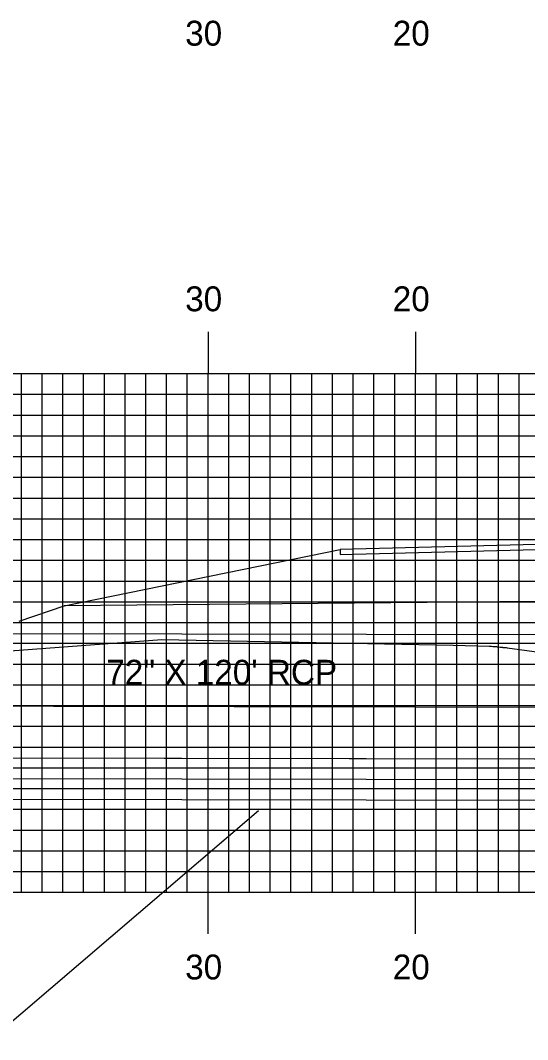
# Model space of a CAD drawing. Extents: x 1774777 to 1775120, y 442591 to 442811.
# Drawn here: x 1774903.64 to 1774928.1, y 442641.57 to 442690.68 of the extents above; entities that cross this region are included whole.
import ezdxf

# ---------------------------------------------------------------- set-up
doc = ezdxf.new("R2010")
doc.units = 0
for name, color, linetype in [('ANNOTATION', 7, 'Continuous'), ('D_Drainage_Culvert', 7, 'Continuous'), ('D_Drainage_Text', 7, 'Continuous'), ('D_Roadway_Edge_Shoulder', 7, 'Continuous'), ('D_Roadway_FinishedGrade', 7, 'Continuous'), ('H_V ANNOTATION', 7, 'Continuous'), ('MAJOR', 7, 'Continuous'), ('MINOR', 7, 'Continuous'), ('S_Roadway_Centerline', 7, 'Continuous')]:
    doc.layers.add(name, color=color, linetype=linetype)

msp = doc.modelspace()

# ---------------------------------------------------------------- linework, layer by layer
at = {"layer": 'ANNOTATION'}
msp.add_lwpolyline([(1774978.969, 442661.903), (1774956.856, 442662.454), (1774942.683, 442662.807), (1774928.511, 442662.681), (1774905.753, 442662.477)], dxfattribs=at)
at = {"layer": 'D_Drainage_Culvert'}
for p, q in [((1774883.795, 442661.172), (1774999.794, 442660.965)), ((1774883.784, 442655.172), (1774999.784, 442654.965)), ((1774883.784, 442654.179), (1774999.784, 442653.972)), ((1774883.784, 442653.179), (1774999.784, 442652.972))]:
    msp.add_line(p, q, dxfattribs=at)
for points in [[(1774883.784, 442655.172), (1774999.784, 442654.965), (1774999.784, 442654.971)], [(1774898.671, 442641.566), (1774902.195, 442641.566), (1774915.113, 442652.609)]]:
    msp.add_lwpolyline(points, dxfattribs=at)
at = {"layer": 'D_Roadway_Edge_Shoulder'}
msp.add_lwpolyline([(1774928.508, 442665.431), (1774919.057, 442665.186), (1774919.057, 442664.936), (1774928.508, 442665.181)], close=True, dxfattribs=at)
at = {"layer": 'D_Roadway_FinishedGrade'}
for p, q in [((1774905.753, 442662.477), (1774919.057, 442665.186)), ((1774903.585, 442661.737), (1774905.753, 442662.477))]:
    msp.add_line(p, q, dxfattribs=at)
msp.add_lwpolyline([(1774887.788, 442657.665), (1775009.789, 442657.447), (1775009.788, 442654.965), (1775009.788, 442652.965)], dxfattribs=at)
at = {"layer": 'MAJOR'}
for p, q in [((1774912.685, 442675.669), (1774912.685, 442673.665)), ((1774922.685, 442675.669), (1774922.685, 442673.665)), ((1774802.685, 442673.665), (1775082.685, 442673.665)), ((1774802.685, 442673.665), (1775082.685, 442673.665)), ((1774912.685, 442648.665), (1774912.685, 442673.665)), ((1774922.685, 442648.665), (1774922.685, 442673.665)), ((1774802.685, 442668.665), (1775082.685, 442668.665)), ((1774802.685, 442663.665), (1775082.685, 442663.665)), ((1774802.685, 442658.665), (1775082.685, 442658.665)), ((1774802.685, 442653.665), (1775082.685, 442653.665)), ((1774802.685, 442648.665), (1775082.685, 442648.665)), ((1774802.685, 442648.665), (1775082.685, 442648.665)), ((1774912.685, 442646.661), (1774912.685, 442648.665)), ((1774922.685, 442646.661), (1774922.685, 442648.665))]:
    msp.add_line(p, q, dxfattribs=at)
at = {"layer": 'MINOR'}
for p, q in [((1774903.685, 442648.665), (1774903.685, 442673.665)), ((1774904.685, 442648.665), (1774904.685, 442673.665)), ((1774905.685, 442648.665), (1774905.685, 442673.665)), ((1774906.685, 442648.665), (1774906.685, 442673.665)), ((1774907.685, 442648.665), (1774907.685, 442673.665)), ((1774908.685, 442648.665), (1774908.685, 442673.665)), ((1774909.685, 442648.665), (1774909.685, 442673.665)), ((1774910.685, 442648.665), (1774910.685, 442673.665)), ((1774911.685, 442648.665), (1774911.685, 442673.665)), ((1774913.685, 442648.665), (1774913.685, 442673.665)), ((1774914.685, 442648.665), (1774914.685, 442673.665)), ((1774915.685, 442648.665), (1774915.685, 442673.665)), ((1774916.685, 442648.665), (1774916.685, 442673.665)), ((1774917.685, 442648.665), (1774917.685, 442673.665)), ((1774918.685, 442648.665), (1774918.685, 442673.665)), ((1774919.685, 442648.665), (1774919.685, 442673.665)), ((1774920.685, 442648.665), (1774920.685, 442673.665)), ((1774921.685, 442648.665), (1774921.685, 442673.665)), ((1774923.685, 442648.665), (1774923.685, 442673.665)), ((1774924.685, 442648.665), (1774924.685, 442673.665)), ((1774925.685, 442648.665), (1774925.685, 442673.665)), ((1774926.685, 442648.665), (1774926.685, 442673.665)), ((1774927.685, 442648.665), (1774927.685, 442673.665)), ((1774802.685, 442672.665), (1775082.685, 442672.665)), ((1774802.685, 442671.665), (1775082.685, 442671.665)), ((1774802.685, 442670.665), (1775082.685, 442670.665)), ((1774802.685, 442669.665), (1775082.685, 442669.665)), ((1774802.685, 442667.665), (1775082.685, 442667.665)), ((1774802.685, 442666.665), (1775082.685, 442666.665)), ((1774802.685, 442665.665), (1775082.685, 442665.665)), ((1774802.685, 442664.665), (1775082.685, 442664.665)), ((1774802.685, 442662.665), (1775082.685, 442662.665)), ((1774802.685, 442661.665), (1775082.685, 442661.665)), ((1774802.685, 442660.665), (1775082.685, 442660.665)), ((1774802.685, 442659.665), (1775082.685, 442659.665)), ((1774802.685, 442657.665), (1775082.685, 442657.665)), ((1774802.685, 442656.665), (1775082.685, 442656.665)), ((1774802.685, 442655.665), (1775082.685, 442655.665)), ((1774802.685, 442654.665), (1775082.685, 442654.665)), ((1774802.685, 442652.665), (1775082.685, 442652.665)), ((1774802.685, 442651.665), (1775082.685, 442651.665)), ((1774802.685, 442650.665), (1775082.685, 442650.665)), ((1774802.685, 442649.665), (1775082.685, 442649.665))]:
    msp.add_line(p, q, dxfattribs=at)
at = {"layer": 'S_Roadway_Centerline'}
msp.add_lwpolyline([(1774900.337, 442660.097), (1774910.451, 442660.852), (1774924.509, 442660.582), (1774926.234, 442660.527), (1774926.264, 442660.525), (1774926.305, 442660.523), (1774926.357, 442660.52), (1774926.416, 442660.516), (1774926.446, 442660.514), (1774926.475, 442660.512), (1774926.503, 442660.51), (1774926.529, 442660.509), (1774926.55, 442660.507), (1774926.571, 442660.505), (1774926.596, 442660.503), (1774926.625, 442660.5), (1774926.657, 442660.496), (1774926.769, 442660.484), (1774926.807, 442660.48), (1774926.844, 442660.476), (1774926.878, 442660.472), (1774926.907, 442660.469), (1774926.932, 442660.467), (1774926.961, 442660.464), (1774926.993, 442660.461), (1774927.028, 442660.458), (1774927.066, 442660.455), (1774927.104, 442660.452), (1774938.139, 442658.954)], dxfattribs=at)

# ---------------------------------------------------------------- texts
at = {"layer": 'D_Drainage_Text'}
msp.add_text('72" X 120\' RCP', height=1.2, dxfattribs=at).set_placement((1774907.777, 442658.668))
at = {"layer": 'H_V ANNOTATION'}
for s, p in [('30', (1774911.583, 442689.465)), ('20', (1774921.593, 442689.465)), ('30', (1774911.583, 442676.665)), ('20', (1774921.593, 442676.665)), ('30', (1774911.583, 442644.465)), ('20', (1774921.593, 442644.465))]:
    msp.add_text(s, height=1.2, dxfattribs=at).set_placement(p)

doc.saveas('drawing.dxf')
